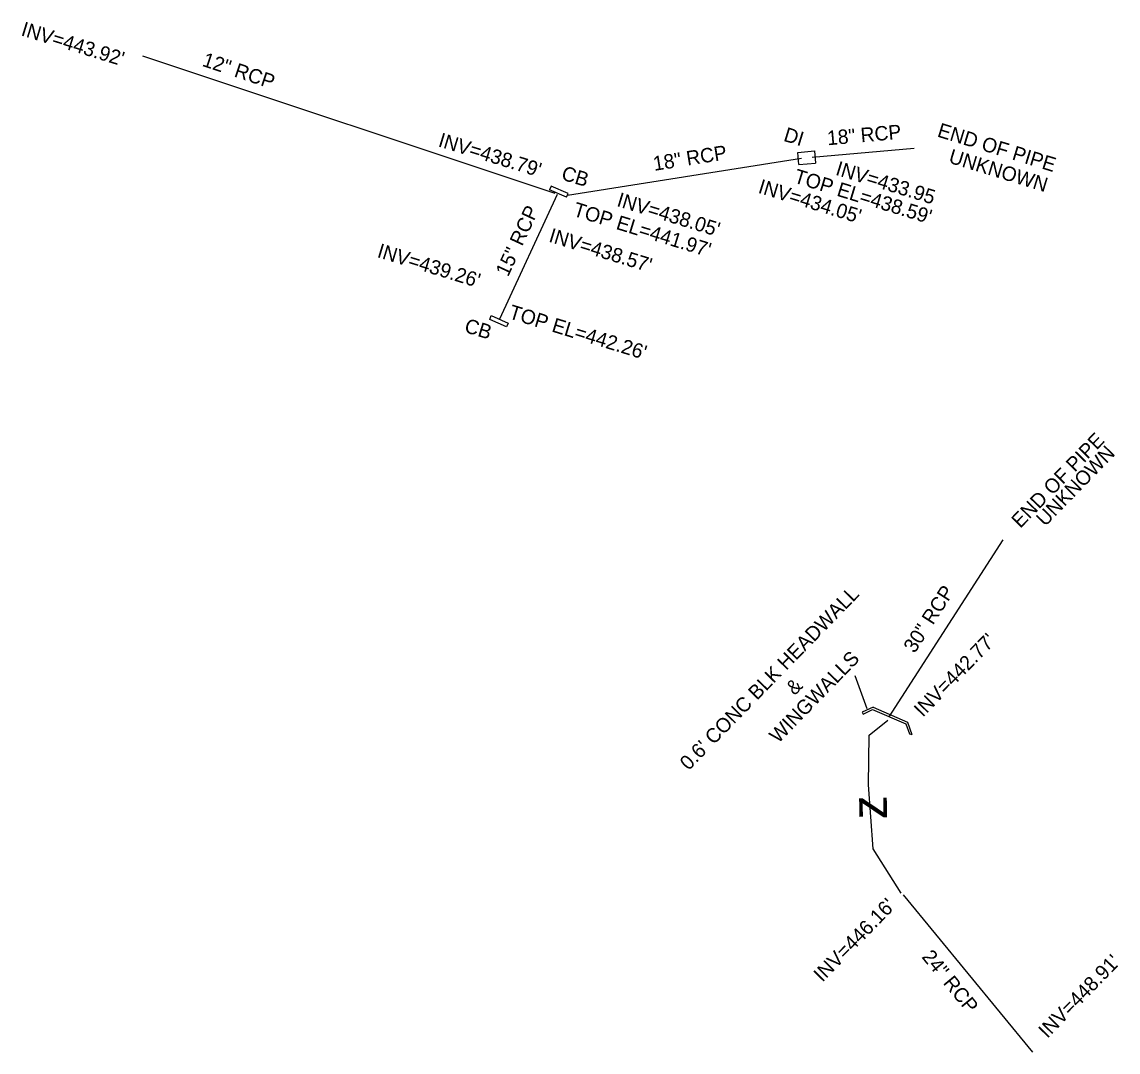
# Model space of a CAD drawing. Extents: x 1975859 to 1978323, y 778892 to 782836.
# Drawn here: x 1976502 to 1976806.2, y 779886.2 to 780172 of the extents above; entities that cross this region are included whole.
import ezdxf

# ---------------------------------------------------------------- set-up
doc = ezdxf.new("R2010")
doc.units = 0
for name, color, linetype in [('Exist Structure Minor Catch Basin', 7, 'Continuous'), ('Exist Structure Minor Catch Basin Text', 7, 'Continuous'), ('Exist Structure Minor Catch Basin Top Elevation', 7, 'Continuous'), ('Exist Structure Minor Drop Inlet', 7, 'Continuous'), ('Exist Structure Minor Drop Inlet Text', 7, 'Continuous'), ('Exist Structure Minor Drop Inlet Top Elevation', 7, 'Continuous'), ('Exist Structure Minor Head and End Wall', 7, 'Continuous'), ('Exist Structure Minor Head and End Wall Leader', 7, 'Continuous'), ('Exist Structure Minor Head and End Wall Text', 7, 'Continuous'), ('Exist Structure Minor Pipes RCP 12 Inch', 7, 'Continuous'), ('Exist Structure Minor Pipes RCP 12 Inch Invert', 7, 'Continuous'), ('Exist Structure Minor Pipes RCP 12 Inch Text', 7, 'Continuous'), ('Exist Structure Minor Pipes RCP 15 Inch', 7, 'Continuous'), ('Exist Structure Minor Pipes RCP 15 Inch Invert', 7, 'Continuous'), ('Exist Structure Minor Pipes RCP 15 Inch Text', 7, 'Continuous'), ('Exist Structure Minor Pipes RCP 18 Inch', 7, 'Continuous'), ('Exist Structure Minor Pipes RCP 18 Inch Invert', 7, 'Continuous'), ('Exist Structure Minor Pipes RCP 18 Inch Text', 7, 'Continuous'), ('Exist Structure Minor Pipes RCP 24 Inch', 7, 'Continuous'), ('Exist Structure Minor Pipes RCP 24 Inch Invert', 7, 'Continuous'), ('Exist Structure Minor Pipes RCP 24 Inch Text', 7, 'Continuous'), ('Exist Structure Minor Pipes RCP 30 Inch', 7, 'Continuous'), ('Exist Structure Minor Pipes RCP 30 Inch Invert', 7, 'Continuous'), ('Exist Structure Minor Pipes RCP 30 Inch Text', 7, 'Continuous'), ('Scratch_Level_8', 7, 'Continuous')]:
    doc.layers.add(name, color=color, linetype=linetype)

msp = doc.modelspace()

# ---------------------------------------------------------------- linework, layer by layer
at = {"layer": 'Exist Structure Minor Catch Basin'}
for p, q in [((1976653.11, 780123.36), (1976648.38, 780125.41)), ((1976636.95, 780088.41), (1976636.51, 780087.38))]:
    msp.add_line(p, q, dxfattribs=at)
for points in [[(1976653.11, 780123.36), (1976653.58, 780124.34), (1976648.9, 780126.44), (1976648.38, 780125.41)], [(1976636.51, 780087.38), (1976631.88, 780089.41), (1976632.23, 780090.54), (1976636.95, 780088.41)]]:
    msp.add_lwpolyline(points, dxfattribs=at)
at = {"layer": 'Exist Structure Minor Drop Inlet'}
msp.add_line((1976717.62, 780132.42), (1976722.23, 780132.78), dxfattribs=at)
msp.add_lwpolyline([(1976717.62, 780132.42), (1976717.3, 780135.77), (1976721.91, 780136.19), (1976722.23, 780132.78)], dxfattribs=at)
at = {"layer": 'Exist Structure Minor Head and End Wall'}
for p, q in [((1976738.21, 779981.85), (1976735.17, 779980.5)), ((1976735.43, 779979.98), (1976738.08, 779981.25)), ((1976738.08, 779981.25), (1976747.26, 779977.25)), ((1976738.21, 779981.85), (1976747.74, 779977.7)), ((1976735.17, 779980.5), (1976735.43, 779979.98)), ((1976747.26, 779977.25), (1976748.28, 779974.48)), ((1976747.74, 779977.7), (1976748.98, 779974.31)), ((1976748.28, 779974.48), (1976748.98, 779974.31))]:
    msp.add_line(p, q, dxfattribs=at)
at = {"layer": 'Exist Structure Minor Head and End Wall Leader'}
msp.add_lwpolyline([(1976736.59, 779981.43), (1976733.19, 779990.6)], dxfattribs=at)
at = {"layer": 'Exist Structure Minor Pipes RCP 12 Inch'}
msp.add_line((1976649.95, 780124.36), (1976535.59, 780162.49), dxfattribs=at)
at = {"layer": 'Exist Structure Minor Pipes RCP 15 Inch'}
msp.add_line((1976634.64, 780089.62), (1976650.6, 780124.19), dxfattribs=at)
at = {"layer": 'Exist Structure Minor Pipes RCP 18 Inch'}
for p, q in [((1976721.29, 780134.44), (1976749.6, 780136.97)), ((1976653.41, 780123.87), (1976718.34, 780134.2))]:
    msp.add_line(p, q, dxfattribs=at)
at = {"layer": 'Exist Structure Minor Pipes RCP 24 Inch'}
msp.add_line((1976782.48, 779886.22), (1976746.66, 779929.8), dxfattribs=at)
at = {"layer": 'Exist Structure Minor Pipes RCP 30 Inch'}
msp.add_line((1976742.63, 779979.17), (1976774.29, 780028.27), dxfattribs=at)
at = {"layer": 'Scratch_Level_8'}
msp.add_lwpolyline([(1976746, 779930.28), (1976738.25, 779942.56), (1976736.95, 779960.35), (1976737.09, 779974.09), (1976742.29, 779978.32)], dxfattribs=at)

# ---------------------------------------------------------------- texts
at = {"layer": 'Exist Structure Minor Catch Basin Text'}
for p in [(1976651.45, 780128.32), (1976624.54, 780086.01)]:
    msp.add_text('CB', height=4, rotation=342.9938, dxfattribs=at).set_placement(p)
at = {"layer": 'Exist Structure Minor Catch Basin Top Elevation'}
for s, p in [("TOP EL=441.97'", (1976654.71, 780118.23)), ("TOP EL=442.26'", (1976636.86, 780089.79))]:
    msp.add_text(s, height=4, rotation=342.9938, dxfattribs=at).set_placement(p)
at = {"layer": 'Exist Structure Minor Drop Inlet Text'}
msp.add_text('DI', height=4, rotation=342.9938, dxfattribs=at).set_placement((1976713.12, 780139.02))
at = {"layer": 'Exist Structure Minor Drop Inlet Top Elevation'}
msp.add_text("TOP EL=438.59'", height=4, rotation=342.9938, dxfattribs=at).set_placement((1976715.95, 780127.45))
at = {"layer": 'Exist Structure Minor Head and End Wall Text'}
for s, p in [("0.6' CONC BLK HEADWALL", (1976687.03, 779964.16)), ('WINGWALLS', (1976711.88, 779971.66)), ('&', (1976716.45, 779984.96))]:
    msp.add_text(s, height=4, rotation=45.7395, dxfattribs=at).set_placement(p)
at = {"layer": 'Exist Structure Minor Pipes RCP 12 Inch Invert'}
for s, p in [("INV=443.92'", (1976501.55, 780168.28)), ("INV=438.79'", (1976617.3, 780137.49))]:
    msp.add_text(s, height=4, rotation=342.9938, dxfattribs=at).set_placement(p)
at = {"layer": 'Exist Structure Minor Pipes RCP 12 Inch Text'}
msp.add_text('12" RCP', height=4, rotation=341.5602, dxfattribs=at).set_placement((1976551.81, 780159.82))
at = {"layer": 'Exist Structure Minor Pipes RCP 15 Inch Invert'}
for s, p in [("INV=438.57'", (1976647.97, 780111.04)), ("INV=439.26'", (1976600.36, 780106.79))]:
    msp.add_text(s, height=4, rotation=342.9938, dxfattribs=at).set_placement(p)
at = {"layer": 'Exist Structure Minor Pipes RCP 15 Inch Text'}
msp.add_text('15" RCP', height=4, rotation=65.2077, dxfattribs=at).set_placement((1976636.91, 780101.09))
at = {"layer": 'Exist Structure Minor Pipes RCP 18 Inch Invert'}
for s, p in [('END OF PIPE', (1976755.78, 780140.21)), ('UNKNOWN', (1976758.92, 780132.98)), ('INV=433.95', (1976727.55, 780129.62)), ("INV=434.05'", (1976706.07, 780124.62)), ("INV=438.05'", (1976666.85, 780120.94))]:
    msp.add_text(s, height=4, rotation=342.9938, dxfattribs=at).set_placement(p)
at = {"layer": 'Exist Structure Minor Pipes RCP 18 Inch Text'}
for rotation, p in [(5.1244, (1976725.61, 780137.73)), (9.035, (1976677.49, 780130.64))]:
    msp.add_text('18" RCP', height=4, rotation=rotation, dxfattribs=at).set_placement(p)
at = {"layer": 'Exist Structure Minor Pipes RCP 24 Inch Invert'}
for s, p in [("INV=446.16'", (1976724.13, 779905.42)), ("INV=448.91'", (1976786.54, 779889.84))]:
    msp.add_text(s, height=4, rotation=45.7395, dxfattribs=at).set_placement(p)
at = {"layer": 'Exist Structure Minor Pipes RCP 24 Inch Text'}
msp.add_text('24" RCP', height=4, rotation=309.4149, dxfattribs=at).set_placement((1976751.52, 779912.55))
at = {"layer": 'Exist Structure Minor Pipes RCP 30 Inch Invert'}
msp.add_text("INV=442.77'", height=4, rotation=45.7395, dxfattribs=at).set_placement((1976752, 779978.92))
at = {"layer": 'Exist Structure Minor Pipes RCP 30 Inch Text'}
for s, rotation, p in [('END OF PIPE', 45.7394, (1976779.04, 780031.35)), ('UNKNOWN', 45.7394, (1976785.9, 780031.82)), ('30" RCP', 57.1873, (1976749.73, 779996.64))]:
    msp.add_text(s, height=4, rotation=rotation, dxfattribs=at).set_placement(p)
at = {"layer": 'Scratch_Level_8'}
msp.add_text('z', height=10, rotation=90.6272, dxfattribs=at).set_placement((1976742.07, 779950.79))

doc.saveas('drawing.dxf')
